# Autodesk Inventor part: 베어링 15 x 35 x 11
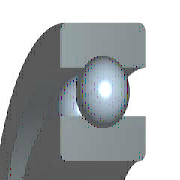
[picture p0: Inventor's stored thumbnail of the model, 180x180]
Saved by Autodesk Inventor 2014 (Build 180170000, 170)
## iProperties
Created: 2012-02
Part Number: 베어링 15 x 35 x 11
Material: 강철, 연강
Description: 깊은 그루브 볼 베어링
Document SubType Name: Modeling
Standard: KS B 2023
Designer: mduedu
Standards Organization: KS
Language: ko-KR
Size Designation: 6202 - 15 x 35 x 11
Categories: <MemberInstance><Categories><Category DisplayName="샤프트 부품" InternalName="7f7aeb1f-a693-4053-b835-cee3144e0d98" Mnemonic="SHFT"><Category DisplayName="베어링" Inter
Density: 1 g/cm^3
Appearance: 강철
IsCustomPart: 1
Author: mduedu
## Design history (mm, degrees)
sketch "스케치" dims "d0" = 5.2 (= -0.26 x WD + 0.26 x BD)
  geometry: L1 (2.9, 12.5)-(8.1, 12.5); L2 (5.5, 12.5)-(5.5, 9.9); L3 (5.5, 12.5)-(5.5, 15.1); L4 (3.568, 10.76)-(0, 10.76); L5 (0, 7.5)-(11, 7.5); L6 (3.568, 14.24)-(0, 14.24); L7 (0, 17.5)-(11, 17.5); L8 (11, 7.5)-(11, 10.76); L9 (7.432, 10.76)-(11, 10.76); L10 (7.432, 14.24)-(11, 14.24); L11 (11, 17.5)-(11, 14.24); L12 (-1.4, 0)-(8.4, 0) reference; L13 (0, -0.3)-(0, 5.3) reference
  constraints: 22 end point, 4 point on line, 2 collinear, 2 perpendicular, 2 symmetric about line, 1 midpoint, 1 parallel, 14 other
  dimensions: "d9" = 15 diameter of L5 L12 (= WD); "d11" = 35 diameter of L7 L12 (= BD); "d12" = 11 distance between parallel lines of L8 L13 (= KB); "d13" = 21.52 diameter of L9 L12 (= 0.326 x BD + 0.674 x WD)
revolve "본체" stored, may be unused: angle "d6" = 90 deg
revolve "볼" stored, may be unused: angle "d7" = 90 deg
pattern_circular "IDS_ARRAYBALL[SIMPL:T]" dims angle "d3" = 360 deg
body "Solid1"
fillet "모깎기1" dims "d1" = 0.6 (= KRS)
other parameters: "WD" = 15 [user parameter; used in 5 equation terms], "BD" = 35 [user parameter; used in 5 equation terms], "KB" = 11 [user parameter; used in 1 equation term], "KRS" = 0.6 [user parameter; used in 1 equation term], "d4" = 0, "d5" = 0, "d8" = 0, "d14" = 0, "d15" = 0, "BBA" = 0 [user parameter], "BC0" = 3750000 [user parameter], "BC" = 7800000 [user parameter], "BR" = 17.5 (= 0.5 x BD) [user parameter], "WR" = 7.5 (= 0.5 x WD) [user parameter]
